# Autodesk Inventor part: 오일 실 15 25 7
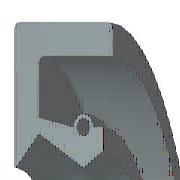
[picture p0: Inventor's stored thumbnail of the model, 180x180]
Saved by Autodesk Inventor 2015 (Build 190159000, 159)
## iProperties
Created: 2012-02
Part Number: 오일 실 15 25 7
Material: 고무
Description: 오일-실
Document SubType Name: Modeling
Standard: KS B 2804
Designer: mduedu
Standards Organization: KS
Language: ko-KR
Size Designation: D - 15 25 7
Categories: <MemberInstance><Categories><Category DisplayName="샤프트 부품" InternalName="7f7aeb1f-a693-4053-b835-cee3144e0d98" Mnemonic="SHFT"><Category DisplayName="실링" Intern
Density: 0.93 g/cm^3
Appearance: 고무 - 검은색 - 버전 1.1
IsCustomPart: 1
Author: mduedu
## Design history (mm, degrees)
revolve "본체" stored, may be unused: angle "d17" = 90 deg
revolve "스프링1" stored, may be unused: angle "d18" = 90 deg
body "Solid1"
sketch "스케치1"
  geometry: L1 (0, 12.5)-(7, 12.5); L2 (7, 10.75)-(1.75, 10.75); L3 (1.75, 9.25)-(4.9, 7.5); L4 (4.9, 7.5)-(0, 7.5); L5 (0, 0)-(9.586, 0) reference; L6 (4.9, 7.5)-(6.3, 8.375); L7 (0, 18)-(0, -3) reference; L8 (-1.941, 0)-(11.507, 0) reference; L9 (4.2, 9.6)-(1.75, 10.09); L10 (1.75, 10.09)-(1.75, 10.75); L11 (0, 12.5)-(0, 7.588); L12 (4.9, 7.5)-(0, 7.5); L13 (1.75, 9.25)-(0.152, 7.528); L14 (7, 12.5)-(7, 10.75); L15 (5.6, 9.6)-(6.3, 9.6); L16 (6.3, 9.6)-(6.3, 8.375); C1 r 0.455 at (4.9, 9.6); A1 r 0.7 centre (4.9, 9.6) between (5.6, 9.6) and (4.2, 9.6); A2 r 0.088 centre (0.088, 7.588) between (0, 7.588) and (0.152, 7.528); 1 further point
  constraints: 28 end point, 5 horizontal alignment, 5 point on line, 4 point on circle, 4 vertical alignment, 3 centre point, 3 tangent, 2 collinear, 2 horizontal, 2 perpendicular, 1 coincident, 1 parallel
  dimensions: "d0" = 25 diameter of L1 L5 (= SD2); "d1" = 1.75 distance of L1.end L2.start (= SD); "d2" = 0.91 diameter of C1 (= SPDI); "d3" = 1.4 diameter of A1 (= SPDA); "d4" = 15 diameter of L3.end L5 (= NND); "d5" = 18.5 diameter of L3.start L5 (= TKDM); "d7" = 20.18 diameter of L9.end L5 (= TKDM + 0.24 x SWDT); "d8" = 1.75 distance between parallel lines of L11 L10 (= SD); "d9" = 4.9 distance from line of L11 C1.centre (= SPDST); "d10" = 19.2 diameter of C1.centre L5 (= HLDM); "d11" = 0.0875 radius of A2 (= 0.25 x LAB); "d12" = 6.3 distance between parallel lines of L11 L16 (= SDI); "d13" = 16.75 diameter of L6.end L5 (= ABDM); "d14" = 7 distance from line of L11 L1.end (= SWDT)
fillet "모깎기1" dims "d6" = 0.3 (= RR)
other parameters: "SD2" = 25 [user parameter; used in 1 equation term], "SWDT" = 7 [user parameter; used in 2 equation terms], "RR" = 0.3 [user parameter; used in 1 equation term], "SD" = 1.75 [user parameter; used in 2 equation terms], "NND" = 15 [user parameter; used in 1 equation term], "SPDA" = 1.4 [user parameter; used in 1 equation term], "SPDI" = 0.91 [user parameter; used in 1 equation term], "TKDM" = 18.5 [user parameter; used in 2 equation terms], "HLDM" = 19.2 [user parameter; used in 1 equation term], "ABDM" = 16.75 [user parameter; used in 1 equation term], "SDI" = 6.3 [user parameter; used in 1 equation term], "SPDST" = 4.9 [user parameter; used in 1 equation term], "LAB" = 0.35 [user parameter; used in 1 equation term], "d15" = 0, "d16" = 0, "d19" = 0
